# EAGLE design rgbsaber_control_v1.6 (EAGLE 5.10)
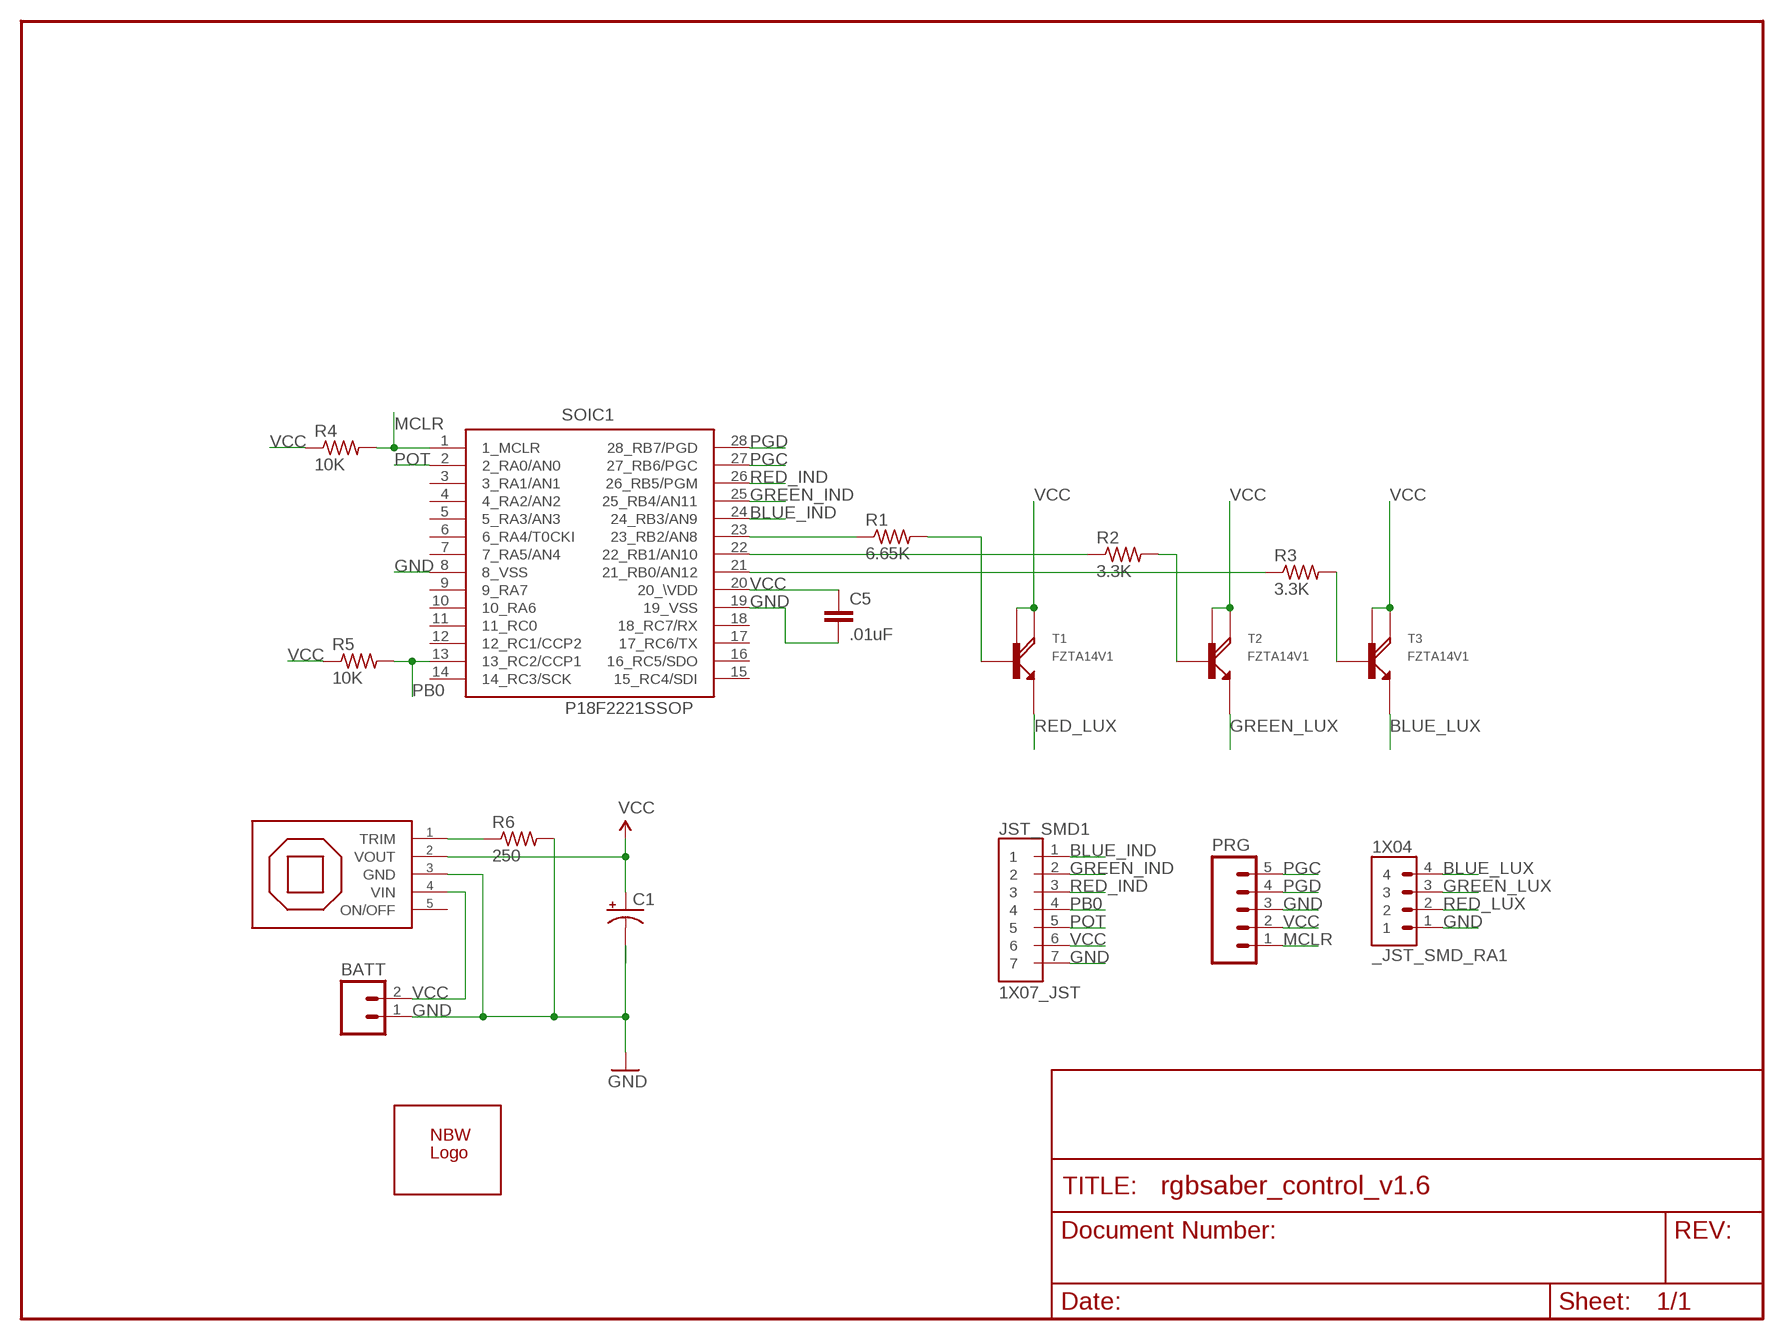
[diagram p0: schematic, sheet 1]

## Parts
_JST_SMD_RA1  1X04  [JST_ZH_SM4_SE_4]
BATT  M02PTH  [1X02]
C1  CPOL-US153CLV-0605  [153CLV-0605]
C5  .01uF  CAP0805  [0805]
JST_SMD1  1X07_JST  [JST_ZH_SM4_TE_7]
PRG  M05PTH  [1X05]
R1  6.65K  R-US_M0805  [M0805]
R2  3.3K  R-US_M0805  [M0805]
R3  3.3K  R-US_M0805  [M0805]
R4  10K  R-US_M0805  [M0805]
R5  10K  R-US_M0805  [M0805]
R6  250  R-US_M0805  [M0805]
REG  REG  OKR-T/3-W12  [1X05_2MM]
SOIC1  P18F2221SSOP  [SSOP-28]
T1  FZTA14V1  [SOT223]
T2  FZTA14V1  [SOT223]
T3  FZTA14V1  [SOT223]
U$5  NBW_LOGOSMALL  [NBW_LOGO]

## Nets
BLUE_IND: JST_SMD1.1 SOIC1.24(24_RB3/AN9)
BLUE_LUX: _JST_SMD_RA1.4 T3.EMIT(E)
GND: _JST_SMD_RA1.1 BATT.1 C1.- C5.2 JST_SMD1.7 PRG.3 R6.2 REG.3(GND) SOIC1.8(8_VSS) SOIC1.19(19_VSS)
GREEN_IND: JST_SMD1.2 SOIC1.25(25_RB4/AN11)
GREEN_LUX: _JST_SMD_RA1.3 T2.EMIT(E)
MCLR: PRG.1 R4.2 SOIC1.1(1_MCLR)
N$1: R6.1 REG.1(TRIM)
N$4: R1.1 SOIC1.23(23_RB2/AN8)
N$5: R1.2 T1.BASE(B)
N$6: R2.1 SOIC1.22(22_RB1/AN10)
N$7: R2.2 T2.BASE(B)
N$8: R3.1 SOIC1.21(21_RB0/AN12)
N$9: R3.2 T3.BASE(B)
PB0: JST_SMD1.4 R5.2 SOIC1.13(13_RC2/CCP1)
PGC: PRG.5 SOIC1.27(27_RB6/PGC)
PGD: PRG.4 SOIC1.28(28_RB7/PGD)
POT: JST_SMD1.5 SOIC1.2(2_RA0/AN0)
PWR: BATT.2 REG.4(VIN)
RED_IND: JST_SMD1.3 SOIC1.26(26_RB5/PGM)
RED_LUX: _JST_SMD_RA1.2 T1.EMIT(E)
VCC: C1.+ C5.1 JST_SMD1.6 PRG.2 R4.1 R5.1 REG.2(VOUT) SOIC1.20(20_\VDD) T1.COLL(C) T1.HEAT(C2) T2.COLL(C) T2.HEAT(C2) T3.COLL(C) T3.HEAT(C2)
Unconnected: REG.5(ON/OFF) SOIC1.3(3_RA1/AN1) SOIC1.4(4_RA2/AN2) SOIC1.5(5_RA3/AN3) SOIC1.6(6_RA4/T0CKI) SOIC1.7(7_RA5/AN4) SOIC1.9(9_RA7) SOIC1.10(10_RA6) SOIC1.11(11_RC0) SOIC1.12(12_RC1/CCP2) SOIC1.14(14_RC3/SCK) SOIC1.15(15_RC4/SDI) SOIC1.16(16_RC5/SDO) SOIC1.17(17_RC6/TX) SOIC1.18(18_RC7/RX)

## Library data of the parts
_JST_SMD_RA1 = NBitWonder:1X04
BATT = SparkFun:M02: Header 2
C1 = rcl:CPOL-US: POLARIZED CAPACITOR, American symbol
C5 = SparkFun:CAP: Capacitor
JST_SMD1 = NBitWonder:1X07_JST
PRG = SparkFun:M05: Header 5 Standard 5-pin 0.1" header. Use with straight break away headers (SKU : PRT-00116), right angle break away headers (PRT-00553), swiss pins (PRT-00743), machine pins (PRT-00117), and female headers (PRT-00115). Molex polarized connector foot print use with SKU : PRT-08230 with associated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
R1-R6 = resistor:R-US_: RESISTOR, American symbol
REG = NBitWonder:OKR-T/3-W12: Device for OKR-T/3-W12 SMPS. SMPS manufactured by Murata Power Solutions. For more information on the device, see http://www.murata-ps.com/data/power/okr-t3-w12.pdf
SOIC1 = purduecer:P18F2221: 28-pin PIC18F series Microcontroller
T1-T3 = purduecer:FZTA14: NPN Darlington Transistor
U$5 = NBitWonder:NBW_LOGO

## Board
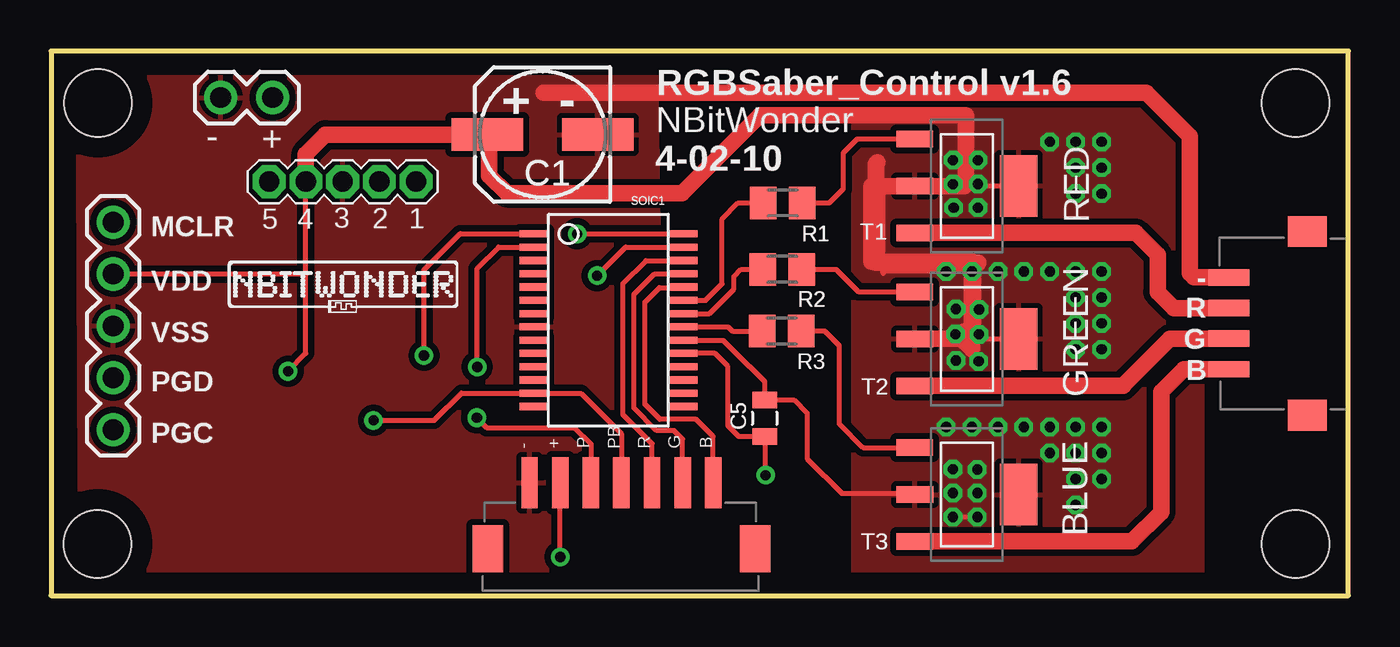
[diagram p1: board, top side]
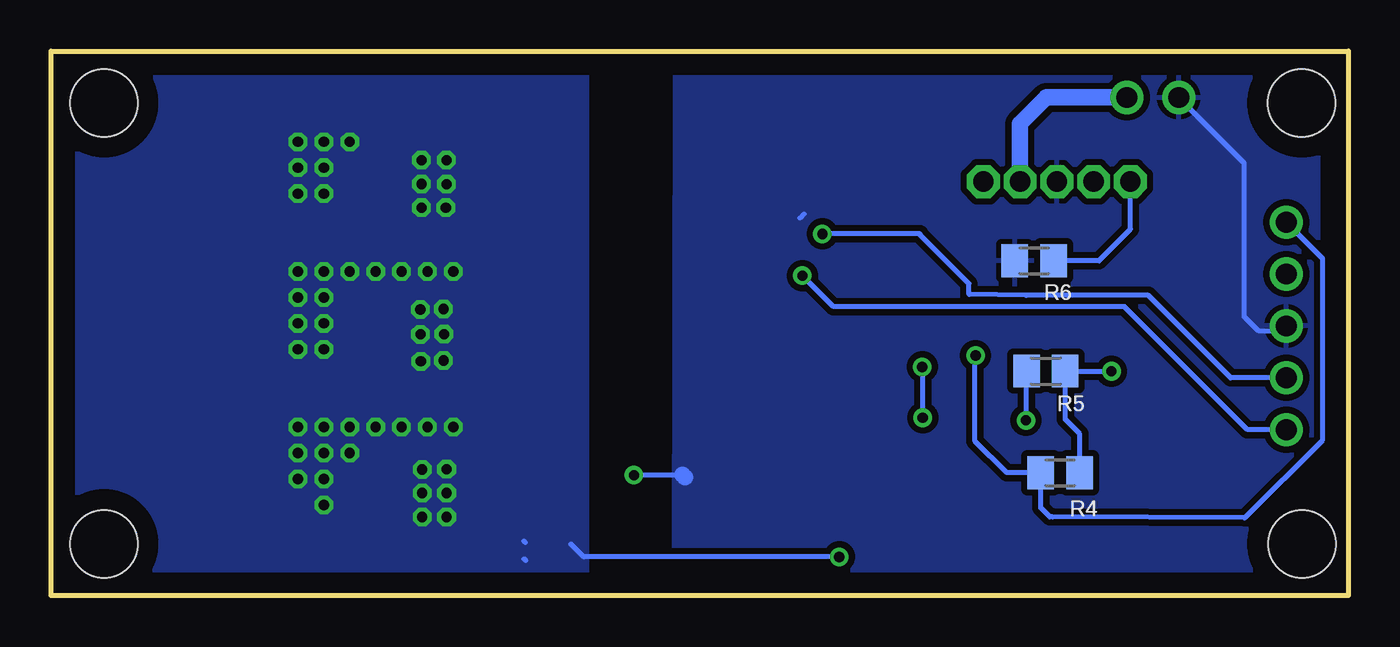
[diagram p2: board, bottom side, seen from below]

Size 63.55 x 26.67 mm. Coordinates in mm from the lower left corner, seen from the top.
Outline: 0,0 63.55,0 63.55,26.66 0,26.67 0,0
Copper layers (1*16): Top 0.035mm / dielectric 1.5mm / Bottom 0.035mm
Design rules "default *": minimum track width 10mil, minimum drill 24mil, track to track 8mil, track to pad 8mil, pad to pad 8mil, via to via 8mil, smd to smd 8mil, copper to edge 40mil, drill to drill 8mil, minimum pad ring 12mil, minimum via ring 8mil, stop-mask expansion 4mil, vias tented up to drill 20mil, thermal gap 10mil

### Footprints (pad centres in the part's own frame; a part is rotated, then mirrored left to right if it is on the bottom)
JST_ZH_SM4_SE_4 = smd 0.8 x 2: 1 -2.25,-1.5; 2 -0.75,-1.5; 3 0.75,-1.5; 4 2.25,-1.5 | smd 1.5 x 1.9: NC0 -4.5,2.35; NC1 4.5,2.35
1X02 = drill 1.016 round: 1 0,0; 2 2.54,0
153CLV-0605 = smd 3.5 x 1.6: + 2.7,0; - -2.7,0
0805 = smd 0.8 x 1.2: 1 -0.9,0; 2 0.9,0
JST_ZH_SM4_TE_7 = smd 0.8 x 2.5: 1 -4.5,-3; 2 -3,-3; 3 -1.5,-3; 4 0,-3; 5 1.5,-3; 6 3,-3; 7 4.5,-3 | smd 1.5 x 2.3: NC0 -6.55,0.25; NC1 6.55,0.25
1X05 = drill 1.016 round: 1 0,0; 2 2.54,0; 3 5.08,0; 4 7.62,0; 5 10.16,0
M0805 = smd 1.3 x 1.6: 1 -0.95,0; 2 0.95,0
1X05_2MM = drill 1 octagon: 1 0,0; 2 1.8,0; 3 3.6,0; 4 5.4,0; 5 7.2,0
SSOP-28 = smd 0.348 x 1.397: 1 -4.225,-3.656; 2 -3.575,-3.656; 3 -2.925,-3.656; 4 -2.275,-3.656; 5 -1.625,-3.656; 6 -0.975,-3.656; 7 -0.325,-3.656; 8 0.325,-3.656; 9 0.975,-3.656; 10 1.625,-3.656; 11 2.275,-3.656; 12 2.925,-3.656; 13 3.575,-3.656; 14 4.225,-3.656; 15 4.225,3.656; 16 3.575,3.656; 17 2.925,3.656; 18 2.275,3.656; 19 1.625,3.656; 20 0.975,3.656; 21 0.325,3.656; 22 -0.325,3.656; 23 -0.975,3.656; 24 -1.625,3.656; 25 -2.275,3.656; 26 -2.925,3.656; 27 -3.575,3.656; 28 -4.225,3.656
SOT223 = smd 0.8 x 1.8: BASE -2.3,-2.55; COLL 0,-2.54; EMIT 2.3,-2.55 | smd 3 x 1.85: HEAT 0,2.54
STAND-OFF = hole 3.302: 0,0

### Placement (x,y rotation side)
_JST_SMD_RA1  59.18,13.34 270 top
BATT  8.31,24.39 0 top
C1  24.08,22.58 180 top
C5  34.95,8.69 270 top
JST_SMD1  27.94,2.54 180 top
PRG  3.05,18.29 270 top
R1  35.84,19.23 0 top
R2  35.81,15.98 0 top
R3  35.79,12.96 0 top
R4  14.12,6.02 180 bottom
R5  14.82,11 180 bottom
R6  15.4,16.4 180 bottom
REG  10.68,20.28 0 top
SOIC1  27.3,13.49 270 top
T1  44.86,20.07 270 top
T2  44.86,12.57 270 top
T3  44.86,4.95 270 top
U$1  [STAND-OFF]  2.29,2.54 0 top
U$2  [STAND-OFF]  2.29,24.13 0 top
U$3  [STAND-OFF]  60.96,24.13 0 top
U$4  [STAND-OFF]  60.96,2.54 0 top
U$5  8.31,13.36 0 top

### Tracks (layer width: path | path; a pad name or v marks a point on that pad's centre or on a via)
BLUE_IND
  Top 0.254: SOIC1.24 30.94,15.09 29.79,15.09 29.08,14.38 29.08,9.37 29.82,8.64 31.59,8.64 32.43,7.8 JST_SMD1.1
BLUE_LUX
  Top 0.813: T3.EMIT 52.95,2.65 54.38,4.09 54.38,9.98 55.49,11.09 _JST_SMD_RA1.4
GND  (via drill 0.5)
  Top 0.254: C5.2 | SOIC1.19 32.51,11.86 33.15,11.23 33.15,8.33 33.69,7.79 C5.2 | v35,5.9 | v35,5.9 35,7.74 C5.2
  Top 0.813: 24.13,24.64 53.65,24.64 55.78,22.51 55.78,16.64 55.78,15.78 55.98,15.59 _JST_SMD_RA1.1
  Bottom 0.254: PRG.3 3.31,12.95 4.39,12.95 5.11,13.67 5.11,21.18 BATT.1 | 26.67,18.69 26.87,18.49 | v35,5.9 32.62,5.9 32.61,5.91
  Bottom 0.813: REG.3 | 32.61,5.91 32.5,5.8
  pour Bottom (isolate 0.305): 33.02,0.61 32.97,25.99 1.47,25.93 1.57,0.59
  pour Top (isolate 0.305): 30.02,0.61 29.64,25.86 1.3,25.81 1.43,0.67
GREEN_IND
  Top 0.254: SOIC1.25 29.56,15.76 28.55,14.75 28.55,9.2 29.67,8.08 30.52,8.08 30.94,7.66 JST_SMD1.2 | SOIC1.25
GREEN_LUX
  Top 0.813: T2.EMIT 52.51,10.27 52.51,10.29 54.81,12.59 _JST_SMD_RA1.3
MCLR  (via drill 0.5)
  Top 0.254: v18.26,11.76 18.26,15.95 20.04,17.73 23.63,17.73 SOIC1.1
  Bottom 0.254: v18.26,11.76 18.29,11.74 18.29,7.57 16.74,6.02 R4.2 15.07,4.3 14.63,3.86 14.5,3.86 5.08,3.81 1.27,7.62 1.27,16.51 PRG.1
N$1
  Bottom 0.254: R6.1 12.22,16.4 10.68,17.94 REG.1
N$4
  Top 0.254: R1.1 33.66,19.23 32.87,18.44 32.87,15.27 32.06,14.46 SOIC1.23
N$5
  Top 0.254: R1.2 38.12,19.23 38.81,19.92 38.81,21.69 39.49,22.37 T1.BASE
N$6
  Top 0.254: SOIC1.22 32.25,13.81 33.45,15.01 33.45,15.62 33.81,15.98 R2.1
N$7
  Top 0.254: 42.29,14.86 T2.BASE 42.3,14.88 39.55,14.88 38.46,15.98 R2.2
N$8
  Top 0.254: SOIC1.21 33.17,13.16 33.38,12.96 R3.1
N$9
  Top 0.254: T3.BASE 39.77,7.25 38.61,8.41 38.61,12.24 37.9,12.95 R3.2
PB0  (via drill 0.5)
  Top 0.254: v15.8,8.59 18.77,8.59 20.1,9.91 SOIC1.13 25.96,9.91 27.94,7.93 JST_SMD1.4
  Bottom 0.254: R5.2 15.77,8.61 v15.8,8.59
PGC  (via drill 0.5)
  Top 0.254: v26.75,15.67 28.14,17.07 SOIC1.27
  Bottom 0.254: v26.75,15.67 25.22,14.15 10.97,14.15 4.95,8.13 PRG.5
PGD  (via drill 0.5)
  Top 0.254: v25.77,17.72 SOIC1.28
  Bottom 0.254: v25.77,17.72 20.99,17.72 20.98,17.71 20.98,17.68 18.58,15.28 18.58,14.75 15.8,14.7 9.8,14.7 5.77,10.67 PRG.4
POT  (via drill 0.5)
  Top 0.254: v20.88,11.2 20.88,16.03 21.92,17.07 SOIC1.2 | v20.85,8.71 21.34,8.23 25.65,8.23 26.44,7.45 JST_SMD1.5
  Bottom 0.254: v20.88,11.2 20.85,11.18 v20.85,8.71
PWR
  Top 0.813: REG.4
  Bottom 0.813: REG.4 16.1,20.3 16.1,23.1 14.8,24.4 BATT.2
RED_IND
  Top 0.254: SOIC1.26 29.13,16.41 28,15.28 28.02,15.26 28.02,8.87 29.44,7.44 JST_SMD1.3
RED_LUX
  Top 0.813: T1.EMIT 53.12,17.77 54.2,16.69 54.2,14.87 54.99,14.08 _JST_SMD_RA1.2
VCC  (via drill 0.5)
  Top 0.254: 44.87,12.57 T2.COLL 43.08,12.57 | 44.87,12.57 T2.HEAT | T1.HEAT T1.COLL 40.77,20.06 40.77,18.51 40.76,18.51 40.76,15.78 40.85,15.88 v43.84,15.88 v45.11,15.88 v45.46,14.01 v45.45,12.8 44.87,12.57 | T3.COLL 42.3,4.97 | v45.37,3.85 v44.18,3.85 | T3.COLL 42.3,4.97 | T3.COLL 42.27,5 38.73,5 37.03,6.71 37.03,8.94 36.39,9.59 C5.1 34.95,10.49 34.21,11.23 34.19,11.23 32.92,12.5 30.98,12.5 SOIC1.20 | v24.94,1.9 JST_SMD1.6 | 12.48,15.71 12.48,11.86 v11.61,10.99 | 12.48,15.71 REG.2 | PRG.2 12.44,15.75 12.48,15.71
  Top 0.813: 40.49,21.24 40.41,21.16 40.41,16.31 45.41,16.31 45.11,16 v45.11,15.88 45.11,12.07 44.6,12.57 T2.COLL 44.73,12.57 44.73,12.96 45.16,12.96 45.16,16.36 40.18,16.36 40.18,20.04 44.73,20.04 44.73,20.27 44.81,20.27 44.81,23.52 34.72,23.52 30.91,19.71 22.33,19.71 21.46,20.58 21.46,22.5 C1.+ 13.44,22.58 12.48,21.63 REG.2
  Bottom 0.254: R4.1 13.13,6.02 13.16,6 13.16,7.93 13.87,8.64 R5.1 v11.61,10.99 | 40.32,2.61 40.39,2.68 | 40.29,1.71 40.39,1.8 | v24.94,1.9 37.46,1.9 38.1,2.54
  other vias: 44.18,21.33 45.4,21.33 45.4,20.16 44.21,19 45.4,19 48.92,22.23 50.19,22.23 51.46,22.23 50.19,20.96 51.46,20.96 51.46,19.69 50.19,19.69 46.38,15.88 44.32,14.04 44.3,12.81 44.32,11.52 45.44,11.48 47.65,15.88 48.92,15.88 50.19,15.88 51.46,15.88 50.19,14.61 51.46,14.61 50.19,13.34 51.46,13.34 50.19,12.07 51.46,12.07 51.46,8.26 51.46,6.99 51.46,5.72 50.19,4.45 50.19,5.72 50.19,6.99 50.19,8.26 48.92,8.26 48.92,6.99 47.65,8.26 46.38,8.26 45.11,8.26 43.84,8.26 44.18,6.19 45.37,6.18 45.37,5.03 44.18,5.03 45.4,20.16 44.18,20.15
  pour Top (isolate 0.305): 39.32,0.86 39.32,25.68 56.36,25.68 56.36,0.76 39.29,0.76 39.29,0.99
  pour Bottom (isolate 0.305): 37.8,0.69 62.59,0.74 62.59,25.86 37.31,25.93 37.31,0.69

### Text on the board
tPlace: RGBSaber_Control v1.6 | + | - | NBitWonder | - | + | 4-02-10 | MCLR | 5 | 4 | 3 | 2 | 1 | RED | - | VDD | R | G | VSS | B | PGD | GREEN | PGC | - | + | P | PB | R | G | B | BLUE
_tNames: C1 | C1 | SOIC1 | SOIC1 | T1 | T1 | R1 | R1 | R2 | R2 | R3 | R3 | T2 | T2 | C5 | C5 | T3 | T3
_bNames: R6 | R6 | R5 | R5 | R4 | R4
